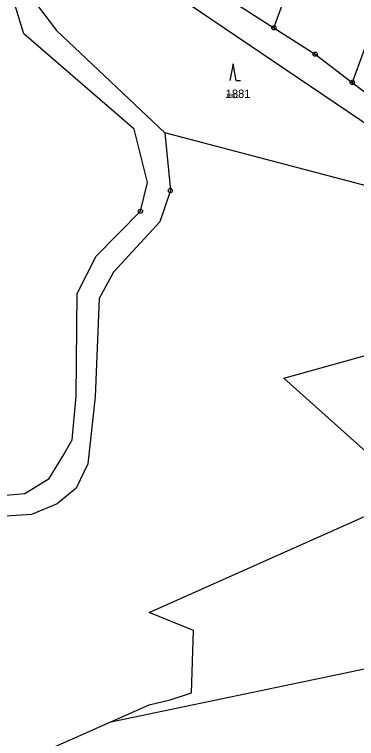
# Model space of a CAD drawing. Extents: x -763628 to -761565, y -976033 to -973833.
# Drawn here: x -763000.2 to -762918.4, y -974969.1 to -974795.9 of the extents above; entities that cross this region are included whole.
import ezdxf

# ---------------------------------------------------------------- set-up
doc = ezdxf.new("R2010")
doc.units = 0
for name, color, linetype in [('KN_cisla parcel 1000', 7, 'Continuous'), ('KN_cisla parcel 500', 7, 'Continuous'), ('KN_hranice parcel', 7, 'Continuous'), ('KN_znacky bodu BP', 7, 'Continuous'), ('KN_znacky kultur', 7, 'Continuous')]:
    doc.layers.add(name, color=color, linetype=linetype)

msp = doc.modelspace()

# ---------------------------------------------------------------- linework, layer by layer
at = {"layer": 'KN_hranice parcel'}
for p, q in [((-762919.45, -974812.19), (-762913.55, -974816.7)), ((-762905.11, -974839.85), (-762964.25, -974824.24)), ((-763022.28, -974985.03), (-762977.1, -974965.05))]:
    msp.add_line(p, q, dxfattribs=at)
for points in [[(-762994.25, -974764.55), (-762982.16, -974767.21), (-762983.38, -974770.25), (-762938.18, -974799.13)], [(-762938.18, -974799.13), (-762926.15, -974766.31), (-762905.42, -974773.91), (-762919.45, -974812.19)], [(-762897.01, -974835.08), (-762982.24, -974777.4), (-762986.77, -974777.36), (-762991.48, -974780.2), (-762995.01, -974786.94), (-762995.15, -974793.13), (-762990.09, -974799.77), (-762964.25, -974824.24)], [(-763002.31, -974910.91), (-762997.68, -974910.47), (-762991.87, -974906.89), (-762988.64, -974901.57), (-762986.34, -974897.62), (-762985.44, -974887.23), (-762985.19, -974862.68), (-762980.61, -974853.7), (-762970.07, -974843), (-762968.4, -974836.12), (-762971.56, -974823.35), (-762997.95, -974800.6), (-763000.68, -974791.38)], [(-762938.18, -974799.13), (-762928.3, -974805.45), (-762919.45, -974812.19)], [(-762964.25, -974824.24), (-762962.91, -974838.04), (-762965.44, -974845.54), (-762976.48, -974857.53), (-762979.92, -974863.89), (-762980.92, -974887.38), (-762982.66, -974903.38), (-762985.41, -974909.19), (-762989.98, -974912.98), (-762996.11, -974915.47), (-763002.23, -974915.92), (-763008, -974915.61), (-763013.7, -974911.77), (-763017.94, -974907.12), (-763020.96, -974899.18)], [(-762904.77, -974910.73), (-762935.76, -974882.9), (-762902.28, -974873.58)], [(-762977.1, -974965.05), (-762967.95, -974961.01), (-762962.99, -974959.8), (-762957.86, -974958.14), (-762957.37, -974943.19), (-762967.97, -974938.94), (-762904.77, -974910.73)], [(-762977.1, -974965.05), (-762894.76, -974947.88), (-762888.41, -974938.82)]]:
    msp.add_lwpolyline(points, dxfattribs=at)
at = {"layer": 'KN_znacky bodu BP'}
for centre, radius in [((-762938.18, -974799.13), 0.5), ((-762938.18, -974799.13), 0.0303), ((-762928.3, -974805.45), 0.5), ((-762928.3, -974805.45), 0.0303), ((-762919.45, -974812.19), 0.5), ((-762919.45, -974812.19), 0.0303), ((-762962.91, -974838.04), 0.5), ((-762962.91, -974838.04), 0.0303), ((-762970.07, -974843), 0.5), ((-762970.07, -974843), 0.0303)]:
    msp.add_circle(centre, radius, dxfattribs=at)
at = {"layer": 'KN_znacky kultur'}
for p, q in [((-762947.94, -974807.75), (-762948.69, -974811.75)), ((-762947.19, -974811.75), (-762947.94, -974807.75)), ((-762947.19, -974811.75), (-762946.19, -974811.75))]:
    msp.add_line(p, q, dxfattribs=at)

# ---------------------------------------------------------------- texts
at = {"layer": 'KN_cisla parcel 1000'}
msp.add_text('1881', height=2, dxfattribs=at).set_placement((-762949.71, -974815.9))
at = {"layer": 'KN_cisla parcel 500'}
msp.add_text('1881', height=1, dxfattribs=at).set_placement((-762949.71, -974815.9))

doc.saveas('drawing.dxf')
